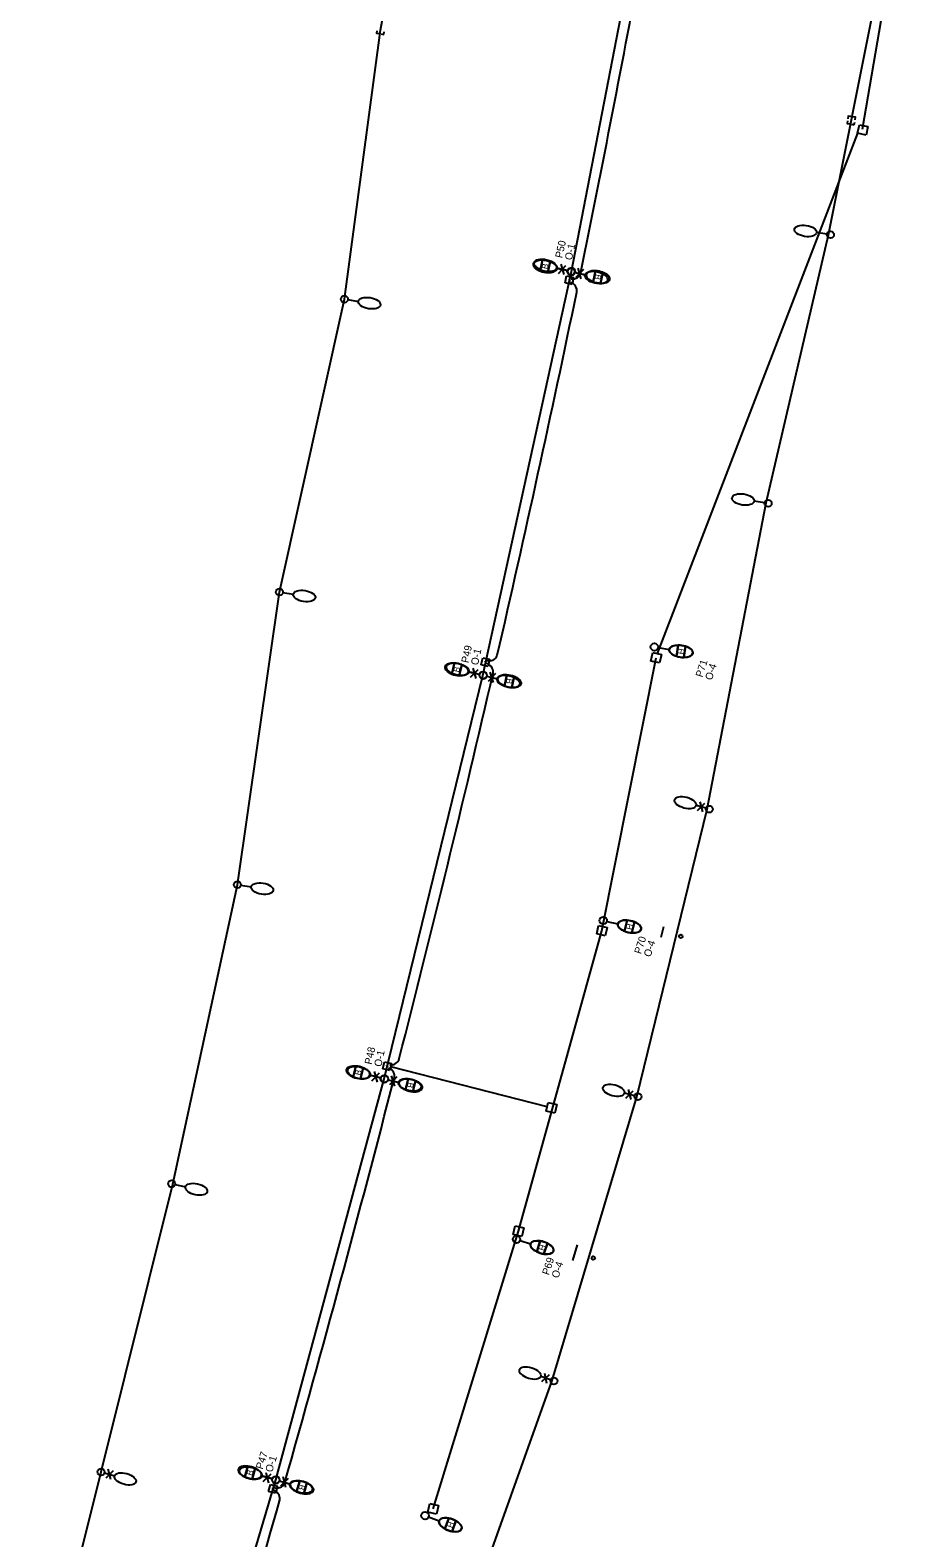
# Model space of a CAD drawing. Extents: x 925407 to 930994, y 604905 to 637063.
# Drawn here: x 930133 to 930735, y 617398 to 618416 of the extents above; entities that cross this region are included whole.
import ezdxf

# ---------------------------------------------------------------- set-up
doc = ezdxf.new("R2010")
doc.units = 0
for name, color, linetype in [('ActivePointCell_dp', 7, 'Continuous'), ('Conduit', 7, 'Continuous'), ('ConduitDB', 7, 'Continuous'), ('ConduitOT', 7, 'Continuous'), ('LiteCond_ep', 7, 'Continuous'), ('Miscellaneous2', 7, 'Continuous'), ('Miscellaneous9', 7, 'Continuous'), ('PoleLight', 7, 'Continuous'), ('PoleLight_ep', 7, 'Continuous'), ('PullBox', 7, 'Continuous')]:
    doc.layers.add(name, color=color, linetype=linetype)

msp = doc.modelspace()

# ---------------------------------------------------------------- linework, layer by layer
at = {"layer": 'ActivePointCell_dp'}
for p, q in [((930558.8, 617803.5), (930560.6, 617810.7)), ((930499.3, 617585.2), (930502.4, 617595.6))]:
    msp.add_line(p, q, dxfattribs=at)
for centre in [(930572.1, 617804), (930513.1, 617586.8)]:
    msp.add_circle(centre, 1.25, dxfattribs=at)
at = {"layer": 'Conduit'}
for p, q in [((930671.8, 618277.7), (930709.2, 618465)), ((930369.5, 618416), (930372.5, 618432.8)), ((930345.1, 618234.3), (930369.5, 618416)), ((930629.8, 618096.8), (930671.8, 618277.7)), ((930301.2, 618036.5), (930345.1, 618234.3)), ((930272.8, 617838.9), (930301.2, 618036.5)), ((930229.3, 617636.7), (930272.8, 617838.9))]:
    msp.add_line(p, q, dxfattribs=at)
at = {"layer": 'ConduitDB'}
for p, q in [((930691.4, 618346.3), (930556.2, 617995)), ((930482, 617688.8), (930376.3, 617715.8))]:
    msp.add_line(p, q, dxfattribs=at)
at = {"layer": 'ConduitOT'}
for p, q in [((930518.9, 617807.8), (930555.6, 617992.1)), ((930462.6, 617604.9), (930518.9, 617807.8)), ((930405, 617417.5), (930462.6, 617604.9))]:
    msp.add_line(p, q, dxfattribs=at)
msp.add_lwpolyline([(930734.9, 618583.7), (930694.7, 618348.9)], dxfattribs=at)
for centre, radius, start, end in [((919236.1, 620547.9), 11500, 348.48654, 349.57918), ((930499.3, 618253.5), 5.5, 258.7271, 349.4943), ((930496.5, 618240.2), 5.5, 347.175, 77.9422), ((919241.4, 620573.8), 11500, 347.03533, 348.28623), ((930440, 617982.7), 5.5, 353.1969, 83.9641), ((930443, 617995.5), 5.5, 250.5001, 341.2673), ((919241.4, 620573.8), 11500, 345.63923, 346.97522), ((930376.7, 617722.7), 5.5, 256.7337, 347.5009), ((930373.4, 617709.6), 5.5, 344.5493, 75.3165), ((919241.4, 620573.8), 11500, 344.15907, 345.57078), ((930296, 617424.3), 5.5, 351.8284, 82.5956), ((930299.6, 617436.9), 5.5, 245.5505, 336.3176), ((919241.4, 620573.8), 11500, 342.85013, 344.10108)]:
    msp.add_arc(centre, radius, start, end, dxfattribs=at)
at = {"layer": 'LiteCond_ep'}
for p, q in [((930498.3, 618253), (930551.7, 618528.9)), ((930438.6, 617980.2), (930498.3, 618253)), ((930590, 617889.9), (930629.8, 618096.8)), ((930372, 617707.8), (930438.6, 617980.2)), ((930542.5, 617695.6), (930590, 617889.9)), ((930298.8, 617437), (930372, 617707.8)), ((930485.3, 617504), (930542.5, 617695.6)), ((930180.8, 617442.3), (930229.3, 617636.7)), ((930418.3, 617315.8), (930485.3, 617504)), ((930132.9, 617250.8), (930180.8, 617442.3)), ((930219.5, 617169.6), (930298.8, 617437))]:
    msp.add_line(p, q, dxfattribs=at)
at = {"layer": 'Miscellaneous2'}
for p, q in [((930478.9, 618260.8), (930477.3, 618253.3)), ((930478.9, 618260.8), (930478.9, 618260.8)), ((930482.3, 618252.3), (930483.9, 618259.8)), ((930483.9, 618259.8), (930483.9, 618259.8)), ((930514.5, 618253.5), (930512.9, 618245.9)), ((930514.5, 618253.5), (930514.5, 618253.5)), ((930517.9, 618244.9), (930519.5, 618252.4)), ((930519.5, 618252.4), (930519.5, 618252.4)), ((930570.4, 618000.7), (930569.2, 617993.2)), ((930574.2, 617992.4), (930575.4, 617999.9)), ((930419.3, 617988.6), (930417.6, 617981.1)), ((930419.3, 617988.6), (930419.3, 617988.6)), ((930422.6, 617980), (930424.3, 617987.4)), ((930424.3, 617987.4), (930424.3, 617987.4)), ((930569.2, 617993.2), (930569.2, 617993.2)), ((930574.2, 617992.4), (930574.2, 617992.4)), ((930454.7, 617980.6), (930453.1, 617973.1)), ((930454.7, 617980.6), (930454.7, 617980.6)), ((930458, 617972), (930459.7, 617979.4)), ((930459.7, 617979.4), (930459.7, 617979.4)), ((930535.9, 617814.9), (930534.2, 617807.5)), ((930539.2, 617806.3), (930540.9, 617813.8)), ((930534.2, 617807.5), (930534.2, 617807.5)), ((930539.2, 617806.3), (930539.2, 617806.3)), ((930352.8, 617716.4), (930351, 617709)), ((930352.8, 617716.4), (930352.8, 617716.4)), ((930355.9, 617707.8), (930357.8, 617715.2)), ((930357.8, 617715.2), (930357.8, 617715.2)), ((930388.1, 617707.7), (930386.3, 617700.3)), ((930388.1, 617707.7), (930388.1, 617707.7)), ((930391.2, 617699), (930393.1, 617706.5)), ((930393.1, 617706.5), (930393.1, 617706.5)), ((930477.3, 617598.3), (930475, 617591)), ((930475, 617591), (930475, 617591)), ((930479.8, 617589.5), (930482.1, 617596.8)), ((930479.8, 617589.5), (930479.8, 617589.5)), ((930279.9, 617446.2), (930277.8, 617438.9)), ((930279.9, 617446.2), (930279.9, 617446.2)), ((930282.7, 617437.5), (930284.8, 617444.8)), ((930284.8, 617444.8), (930284.8, 617444.8)), ((930314.9, 617436.3), (930312.8, 617428.9)), ((930314.9, 617436.3), (930314.9, 617436.3)), ((930317.7, 617427.5), (930319.8, 617434.9)), ((930319.8, 617434.9), (930319.8, 617434.9)), ((930412.9, 617403.9), (930415.5, 617411.1)), ((930415.5, 617411.1), (930415.5, 617411.1)), ((930420.3, 617409.4), (930417.7, 617402.1)), ((930420.3, 617409.4), (930420.3, 617409.4))]:
    msp.add_line(p, q, dxfattribs=at)
for centre, major_axis, start_param, end_param in [((930480.6, 618256.5), (7.91, -1.63), 1.249648, 1.891946), ((930480.6, 618256.5), (7.91, -1.63), 4.391241, 4.391271), ((930480.6, 618256.5), (7.91, -1.63), 4.391271, 5.033538), ((930516.2, 618249.2), (7.91, -1.63), 1.249648, 1.891946), ((930516.2, 618249.2), (7.91, -1.63), 4.391241, 4.391271), ((930516.2, 618249.2), (7.91, -1.63), 4.391271, 5.033538), ((930572.3, 617996.5), (-7.98, 1.27), 4.391271, 5.033538), ((930572.3, 617996.5), (-7.98, 1.27), 4.391241, 4.391271), ((930420.9, 617984.3), (7.88, -1.77), 1.249648, 1.891946), ((930572.3, 617996.5), (-7.98, 1.27), 1.249648, 1.891946), ((930420.9, 617984.3), (7.88, -1.77), 4.391241, 4.391271), ((930420.9, 617984.3), (7.88, -1.77), 4.391271, 5.033538), ((930456.4, 617976.3), (7.88, -1.77), 1.249648, 1.891946), ((930456.4, 617976.3), (7.88, -1.77), 4.391241, 4.391271), ((930456.4, 617976.3), (7.88, -1.77), 4.391271, 5.033538), ((930537.5, 617810.6), (-7.88, 1.79), 4.391271, 5.033538), ((930537.5, 617810.6), (-7.88, 1.79), 4.391241, 4.391271), ((930537.5, 617810.6), (-7.88, 1.79), 1.249648, 1.891946), ((930354.4, 617712.1), (7.84, -1.94), 1.249648, 1.891946), ((930354.4, 617712.1), (7.84, -1.94), 4.391241, 4.391271), ((930354.4, 617712.1), (7.84, -1.94), 4.391271, 5.033538), ((930389.7, 617703.4), (7.84, -1.94), 4.391241, 4.391271), ((930389.7, 617703.4), (7.84, -1.94), 4.391271, 5.033538), ((930389.7, 617703.4), (7.84, -1.94), 1.249648, 1.891946), ((930478.5, 617593.9), (-7.71, 2.42), 4.391271, 5.033538), ((930478.5, 617593.9), (-7.71, 2.42), 1.249648, 1.891946), ((930478.5, 617593.9), (-7.71, 2.42), 4.391241, 4.391271), ((930281.3, 617441.9), (7.77, -2.22), 1.249648, 1.891946), ((930281.3, 617441.9), (7.77, -2.22), 4.391241, 4.391271), ((930281.3, 617441.9), (7.77, -2.22), 4.391271, 5.033538), ((930316.3, 617431.9), (7.77, -2.22), 1.249648, 1.891946), ((930316.3, 617431.9), (7.77, -2.22), 4.391241, 4.391271), ((930316.3, 617431.9), (7.77, -2.22), 4.391271, 5.033538), ((930416.6, 617406.6), (-7.59, 2.76), 4.39124, 5.033537), ((930416.6, 617406.6), (-7.59, 2.76), 1.249648, 1.891914), ((930416.6, 617406.6), (-7.59, 2.76), 1.891914, 1.891945)]:
    msp.add_ellipse(centre, major_axis=major_axis, ratio=0.5, start_param=start_param, end_param=end_param, dxfattribs=at)
at = {"layer": 'PoleLight'}
for p, q in [((930477.3, 618253.3), (930478.9, 618260.8)), ((930483.9, 618259.8), (930482.3, 618252.3)), ((930495.9, 618253.4), (930488.5, 618254.9)), ((930500.9, 618252.3), (930508.3, 618250.8)), ((930512.9, 618245.9), (930514.5, 618253.5)), ((930519.5, 618252.4), (930517.9, 618244.9)), ((930556.8, 617999), (930564.3, 617997.8)), ((930569.2, 617993.2), (930570.4, 618000.7)), ((930575.4, 617999.9), (930574.2, 617992.4)), ((930417.6, 617981.1), (930419.3, 617988.6)), ((930424.3, 617987.4), (930422.6, 617980)), ((930436.2, 617980.8), (930428.8, 617982.5)), ((930441.1, 617979.7), (930448.5, 617978)), ((930453.1, 617973.1), (930454.7, 617980.6)), ((930459.7, 617979.4), (930458, 617972)), ((930522.3, 617814.1), (930529.6, 617812.4)), ((930534.2, 617807.5), (930535.9, 617814.9)), ((930540.9, 617813.8), (930539.2, 617806.3)), ((930351, 617709), (930352.8, 617716.4)), ((930357.8, 617715.2), (930355.9, 617707.8)), ((930369.6, 617708.3), (930362.2, 617710.2)), ((930374.5, 617707.1), (930381.8, 617705.3)), ((930386.3, 617700.3), (930388.1, 617707.7)), ((930393.1, 617706.5), (930391.2, 617699)), ((930463.6, 617598.6), (930470.8, 617596.3)), ((930475, 617591), (930477.3, 617598.3)), ((930482.1, 617596.8), (930479.8, 617589.5)), ((930277.8, 617438.9), (930279.9, 617446.2)), ((930284.8, 617444.8), (930282.7, 617437.5)), ((930296.4, 617437.6), (930289.1, 617439.6)), ((930301.2, 617436.2), (930308.5, 617434.1)), ((930312.8, 617428.9), (930314.9, 617436.3)), ((930319.8, 617434.9), (930317.7, 617427.5)), ((930401.9, 617412), (930409, 617409.4)), ((930415.5, 617411.1), (930412.9, 617403.9)), ((930417.7, 617402.1), (930420.3, 617409.4))]:
    msp.add_line(p, q, dxfattribs=at)
for centre in [(930498.4, 618252.9), (930498.4, 618252.9), (930554.3, 617999.4), (930554.3, 617999.4), (930438.7, 617980.3), (930438.7, 617980.3), (930519.8, 617814.7), (930519.8, 617814.7), (930372, 617707.7), (930372, 617707.7), (930461.2, 617599.4), (930461.2, 617599.4), (930298.8, 617436.9), (930298.8, 617436.9), (930399.5, 617412.8), (930399.5, 617412.8)]:
    msp.add_circle(centre, 2.52, dxfattribs=at)
for centre, major_axis in [((930480.6, 618256.5), (7.91, -1.63)), ((930516.2, 618249.2), (7.91, -1.63)), ((930572.3, 617996.5), (-7.98, 1.27)), ((930420.9, 617984.3), (7.88, -1.77)), ((930456.4, 617976.3), (7.88, -1.77)), ((930537.5, 617810.6), (-7.88, 1.79)), ((930354.4, 617712.1), (7.84, -1.94)), ((930389.7, 617703.4), (7.84, -1.94)), ((930478.5, 617593.9), (-7.71, 2.42)), ((930281.3, 617441.9), (7.77, -2.22)), ((930316.3, 617431.9), (7.77, -2.22)), ((930416.6, 617406.6), (-7.59, 2.76))]:
    msp.add_ellipse(centre, major_axis=major_axis, ratio=0.5, dxfattribs=at)
for centre, major_axis, start_param, end_param in [((930480.6, 618256.5), (7.91, -1.63), 1.891945, 4.391241), ((930480.6, 618256.5), (7.91, -1.63), 0.847605, 1.249648), ((930480.6, 618256.5), (7.91, -1.63), 5.033538, 6.283185), ((930480.6, 618256.5), (7.91, -1.63), 0, 0.847605), ((930516.2, 618249.2), (7.91, -1.63), 1.891945, 4.391241), ((930516.2, 618249.2), (7.91, -1.63), 0.847605, 1.249648), ((930516.2, 618249.2), (7.91, -1.63), 0, 0.847605), ((930516.2, 618249.2), (7.91, -1.63), 5.033538, 6.283185), ((930572.3, 617996.5), (-7.98, 1.27), 0, 0.847605), ((930572.3, 617996.5), (-7.98, 1.27), 5.033538, 6.283185), ((930572.3, 617996.5), (-7.98, 1.27), 1.891945, 4.391241), ((930420.9, 617984.3), (7.88, -1.77), 1.891945, 4.391241), ((930420.9, 617984.3), (7.88, -1.77), 0.847605, 1.249648), ((930420.9, 617984.3), (7.88, -1.77), 0, 0.847605), ((930572.3, 617996.5), (-7.98, 1.27), 0.847605, 1.249648), ((930420.9, 617984.3), (7.88, -1.77), 5.033538, 6.283185), ((930456.4, 617976.3), (7.88, -1.77), 1.891945, 4.391241), ((930456.4, 617976.3), (7.88, -1.77), 5.033538, 6.283185), ((930456.4, 617976.3), (7.88, -1.77), 0.847605, 1.249648), ((930456.4, 617976.3), (7.88, -1.77), 0, 0.847605), ((930537.5, 617810.6), (-7.88, 1.79), 0, 0.847605), ((930537.5, 617810.6), (-7.88, 1.79), 5.033538, 6.283185), ((930537.5, 617810.6), (-7.88, 1.79), 1.891945, 4.391241), ((930537.5, 617810.6), (-7.88, 1.79), 0.847605, 1.249648), ((930354.4, 617712.1), (7.84, -1.94), 1.891945, 4.391241), ((930354.4, 617712.1), (7.84, -1.94), 5.033538, 6.283185), ((930354.4, 617712.1), (7.84, -1.94), 0.847605, 1.249648), ((930354.4, 617712.1), (7.84, -1.94), 0, 0.847605), ((930389.7, 617703.4), (7.84, -1.94), 1.891945, 4.391241), ((930389.7, 617703.4), (7.84, -1.94), 5.033538, 6.283185), ((930389.7, 617703.4), (7.84, -1.94), 0.847605, 1.249648), ((930389.7, 617703.4), (7.84, -1.94), 0, 0.847605), ((930478.5, 617593.9), (-7.71, 2.42), 5.033538, 6.283185), ((930478.5, 617593.9), (-7.71, 2.42), 0, 0.847605), ((930478.5, 617593.9), (-7.71, 2.42), 0.847605, 1.249648), ((930478.5, 617593.9), (-7.71, 2.42), 1.891945, 4.391241), ((930281.3, 617441.9), (7.77, -2.22), 1.891945, 4.391241), ((930281.3, 617441.9), (7.77, -2.22), 5.033538, 6.283185), ((930281.3, 617441.9), (7.77, -2.22), 0.847605, 1.249648), ((930281.3, 617441.9), (7.77, -2.22), 0, 0.847605), ((930316.3, 617431.9), (7.77, -2.22), 1.891945, 4.391241), ((930316.3, 617431.9), (7.77, -2.22), 0.847605, 1.249648), ((930316.3, 617431.9), (7.77, -2.22), 5.033538, 6.283185), ((930316.3, 617431.9), (7.77, -2.22), 0, 0.847605), ((930416.6, 617406.6), (-7.59, 2.76), 0, 1.249648), ((930416.6, 617406.6), (-7.59, 2.76), 5.43558, 6.283185), ((930416.6, 617406.6), (-7.59, 2.76), 5.033537, 5.43558), ((930416.6, 617406.6), (-7.59, 2.76), 1.891945, 4.39124)]:
    msp.add_ellipse(centre, major_axis=major_axis, ratio=0.5, start_param=start_param, end_param=end_param, dxfattribs=at)
at = {"layer": 'PoleLight_ep'}
for p, q in [((930670.8, 618278.2), (930663.8, 618279.3)), ((930495.6, 618253.6), (930488.5, 618255.3)), ((930489.6, 618251.7), (930494.6, 618257.1)), ((930491.1, 618257.9), (930493.1, 618250.9)), ((930500.4, 618252.4), (930507.5, 618250.7)), ((930506.4, 618254.3), (930501.4, 618249)), ((930504.9, 618248.1), (930502.8, 618255.2)), ((930347.4, 618234), (930354.4, 618232.8)), ((930628.7, 618096.8), (930621.7, 618097.9)), ((930303.5, 618036.1), (930310.5, 618035)), ((930431.7, 617985.2), (930433.8, 617978.1)), ((930436.3, 617980.8), (930429.1, 617982.6)), ((930430.2, 617979), (930435.3, 617984.3)), ((930441, 617979.7), (930448.2, 617978)), ((930447.1, 617981.6), (930442, 617976.2)), ((930445.6, 617975.4), (930443.5, 617982.4)), ((930583.4, 617888.9), (930588.4, 617893.9)), ((930585, 617894.8), (930586.8, 617888)), ((930589.3, 617890.5), (930582.5, 617892.4)), ((930275.1, 617838.5), (930282.1, 617837.4)), ((930369.7, 617708.4), (930362.5, 617710.1)), ((930363.6, 617706.5), (930368.7, 617711.8)), ((930365.1, 617712.7), (930367.2, 617705.6)), ((930379, 617702.9), (930376.9, 617709.9)), ((930374.4, 617707.2), (930381.6, 617705.5)), ((930380.5, 617709.1), (930375.4, 617703.8)), ((930535, 617694.7), (930540, 617699.7)), ((930536.6, 617700.6), (930538.4, 617693.8)), ((930540.9, 617696.3), (930534.1, 617698.1)), ((930230.8, 617636.4), (930237.7, 617634.9)), ((930484.3, 617504.5), (930477.6, 617506.7)), ((930478.3, 617503.3), (930483.5, 617508)), ((930480.2, 617509.1), (930481.6, 617502.2)), ((930183, 617441.6), (930189.8, 617439.7)), ((930188.9, 617443.1), (930183.9, 617438.2)), ((930187.3, 617437.2), (930185.6, 617444.1)), ((930296.4, 617437.5), (930289.3, 617439.4)), ((930290.3, 617435.8), (930295.5, 617441)), ((930292, 617442), (930293.9, 617434.9)), ((930301.1, 617436.2), (930308.2, 617434.3)), ((930307.2, 617437.9), (930302, 617432.7)), ((930305.6, 617431.8), (930303.7, 617438.9))]:
    msp.add_line(p, q, dxfattribs=at)
for centre, radius in [((930673.2, 618277.8), 2.37), ((930498, 618253), 2.45), ((930345.1, 618234.3), 2.37), ((930631.1, 618096.4), 2.37), ((930301.2, 618036.5), 2.37), ((930438.7, 617980.3), 2.45), ((930591.5, 617889.9), 2.35), ((930272.8, 617838.9), 2.37), ((930372.1, 617707.8), 2.45), ((930543.2, 617695.7), 2.35), ((930228.5, 617636.9), 2.37), ((930486.5, 617503.8), 2.35), ((930180.8, 617442.3), 2.35), ((930298.8, 617436.9), 2.45)]:
    msp.add_circle(centre, radius, dxfattribs=at)
for centre, major_axis in [((930656.3, 618280.4), (-7.48, 1.16)), ((930480.8, 618257.1), (-7.62, 1.83)), ((930515.1, 618248.9), (7.62, -1.83)), ((930361.9, 618231.6), (7.47, -1.22)), ((930614.2, 618099), (-7.48, 1.16)), ((930318, 618033.8), (7.47, -1.22)), ((930421.5, 617984.4), (-7.62, 1.83)), ((930455.8, 617976.1), (7.62, -1.83)), ((930575.2, 617894.3), (-7.27, 1.98)), ((930289.6, 617836.2), (7.47, -1.22)), ((930354.9, 617711.9), (-7.62, 1.83)), ((930389.2, 617703.7), (7.62, -1.83)), ((930526.8, 617700), (-7.27, 1.94)), ((930245.1, 617633.2), (7.39, -1.64)), ((930470.4, 617509.1), (-7.16, 2.34)), ((930281.8, 617441.5), (-7.56, 2.06)), ((930197.1, 617437.6), (7.24, -2.06)), ((930315.8, 617432.2), (7.56, -2.06))]:
    msp.add_ellipse(centre, major_axis=major_axis, ratio=0.5, dxfattribs=at)
at = {"layer": 'PullBox'}
for p, q in [((930691.4, 618346.3), (930692.8, 618352.1)), ((930692.8, 618352.1), (930698.5, 618350.8)), ((930697.2, 618345), (930691.4, 618346.3)), ((930698.5, 618350.8), (930697.2, 618345)), ((930494.1, 618245.3), (930495.1, 618250)), ((930495.1, 618250), (930499.8, 618249)), ((930498.8, 618244.3), (930494.1, 618245.3)), ((930499.8, 618249), (930498.8, 618244.3)), ((930552, 617989.9), (930553.3, 617995.7)), ((930553.3, 617995.7), (930559.1, 617994.4)), ((930437.3, 617987.4), (930438.4, 617992.1)), ((930442, 617986.3), (930437.3, 617987.4)), ((930438.4, 617992.1), (930443.1, 617991.1)), ((930443.1, 617991.1), (930442, 617986.3)), ((930557.8, 617988.6), (930552, 617989.9)), ((930559.1, 617994.4), (930557.8, 617988.6)), ((930515.4, 617805.6), (930516.7, 617811.3)), ((930521.1, 617804.3), (930515.4, 617805.6)), ((930516.7, 617811.3), (930522.4, 617810)), ((930522.4, 617810), (930521.1, 617804.3)), ((930371, 617714.6), (930372.1, 617719.3)), ((930375.7, 617713.5), (930371, 617714.6)), ((930372.1, 617719.3), (930376.8, 617718.2)), ((930376.8, 617718.2), (930375.7, 617713.5)), ((930481.3, 617685.9), (930482.6, 617691.7)), ((930482.6, 617691.7), (930488.4, 617690.4)), ((930488.4, 617690.4), (930487.1, 617684.6)), ((930487.1, 617684.6), (930481.3, 617685.9)), ((930459, 617602.7), (930460.4, 617608.5)), ((930460.4, 617608.5), (930466.1, 617607.1)), ((930464.8, 617601.4), (930459, 617602.7)), ((930466.1, 617607.1), (930464.8, 617601.4)), ((930293.8, 617429.2), (930295.2, 617433.9)), ((930298.5, 617427.9), (930293.8, 617429.2)), ((930295.2, 617433.9), (930299.8, 617432.6)), ((930299.8, 617432.6), (930298.5, 617427.9)), ((930401.4, 617415.2), (930402.8, 617421)), ((930407.2, 617413.9), (930401.4, 617415.2)), ((930402.8, 617421), (930408.5, 617419.7)), ((930408.5, 617419.7), (930407.2, 617413.9))]:
    msp.add_line(p, q, dxfattribs=at)
for points in [[(930367, 618415.6), (930366.7, 618413.9), (930368.3, 618413.6)], [(930369.9, 618413.4), (930371.6, 618413.1)], [(930371.6, 618413.1), (930371.9, 618414.8)], [(930684.7, 618354.7), (930684.4, 618353), (930686.1, 618352.7)], [(930686.9, 618357.6), (930685.2, 618357.9), (930684.9, 618356.1)], [(930687.6, 618352.4), (930689.3, 618352.1)], [(930689.9, 618355.3), (930690.2, 618357.1), (930688.4, 618357.4)], [(930689.3, 618352.1), (930689.6, 618353.8)]]:
    msp.add_lwpolyline(points, dxfattribs=at)

# ---------------------------------------------------------------- texts
at = {"layer": 'ActivePointCell_dp'}
for s, rotation, p in [('P50', 77.5026, (930492.1, 618261.7)), ('O-1', 77.5026, (930498.6, 618260.3)), ('P49', 77.5026, (930428.7, 617988.3)), ('O-1', 77.5026, (930435.2, 617986.8)), ('P71', 72.2133, (930586.7, 617978.6)), ('O-4', 72.2133, (930593.1, 617976.6)), ('P70', 72.2133, (930545.3, 617791.7)), ('O-4', 72.2133, (930551.7, 617789.7)), ('P48', 77.5026, (930363.4, 617717.1)), ('O-1', 77.5026, (930369.9, 617715.6)), ('P69', 72.2133, (930483.1, 617574.9)), ('O-4', 72.2133, (930489.5, 617572.8)), ('P47', 72.2133, (930289.8, 617443.7)), ('O-1', 72.2133, (930296.2, 617441.7))]:
    msp.add_text(s, height=5, rotation=rotation, dxfattribs=at).set_placement(p)
at = {"layer": 'Miscellaneous9'}
for s, rotation, p in [('B', 78.355, (930482.2, 618254.3)), ('B', 258.355, (930514.6, 618251.4)), ('H', 260.9683, (930570.6, 617998.7)), ('B', 77.3087, (930422.5, 617982)), ('B', 257.3087, (930454.8, 617978.5)), ('H', 257.2145, (930535.9, 617812.9)), ('B', 76.0966, (930355.9, 617709.8)), ('B', 256.0966, (930388.1, 617705.7)), ('H', 252.5456, (930477.1, 617596.3)), ('B', 74.0754, (930282.8, 617439.5)), ('B', 254.0754, (930314.8, 617434.2)), ('H', 70.0454, (930417.9, 617404.1))]:
    msp.add_text(s, height=4.08, rotation=rotation, dxfattribs=at).set_placement(p)
at = {"layer": 'PullBox'}
for rotation, p in [(78.324, (930497.7, 618246.3)), (77.2786, (930441, 617988.4)), (76.2344, (930374.7, 617715.5)), (74.0759, (930297.6, 617430))]:
    msp.add_text('J', height=1.94, rotation=rotation, dxfattribs=at).set_placement(p)

doc.saveas('drawing.dxf')
